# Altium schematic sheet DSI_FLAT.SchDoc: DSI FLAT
size A4; Author: Silvio Navaretti; CompanyName: Arduino SRL; DrawnBy: Silvio Navaretti; Engineer: Silvio Navaretti; Organization: Arduino SRL; DocumentNumber: ASX00083; SheetNumber: 7; SheetTotal: 11; RevAuthor: Silvio Navaretti
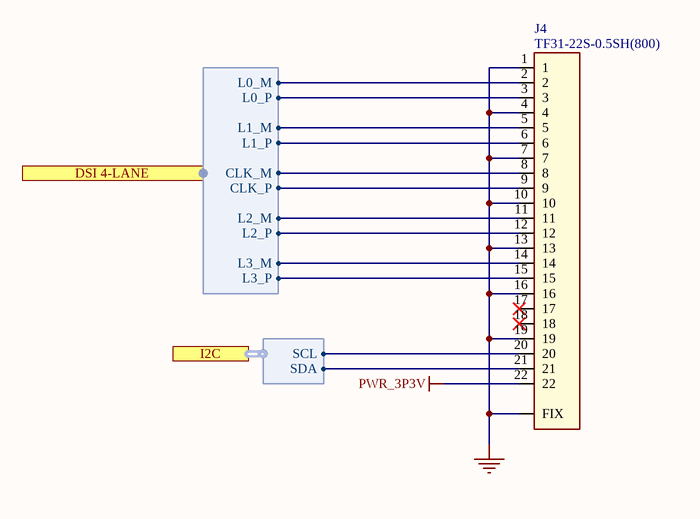
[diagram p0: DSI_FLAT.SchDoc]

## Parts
J4  TF31-22S-0.5SH(800)  [TF31-22S-0.5SH(800)]

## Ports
DSI 4-LANE (harness IMOLA_DSI), I2C (harness I2C)

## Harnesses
I2C: SDA, SCL
IMOLA_DSI: L1_P, L1_M, L3_P, L3_M, CLK_P, CLK_M, L0_P, L0_M, L2_P, L2_M

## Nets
GND: J4.1 J4.4 J4.7 J4.10 J4.13 J4.16 J4.19 J4.FIX
PWR_3P3V: J4.22
NetJ4_2: J4.2 ; port DSI 4-LANE.L0_M
NetJ4_3: J4.3 ; port DSI 4-LANE.L0_P
NetJ4_5: J4.5 ; port DSI 4-LANE.L1_M
NetJ4_6: J4.6 ; port DSI 4-LANE.L1_P
NetJ4_8: J4.8 ; port DSI 4-LANE.CLK_M
NetJ4_9: J4.9 ; port DSI 4-LANE.CLK_P
NetJ4_11: J4.11 ; port DSI 4-LANE.L2_M
NetJ4_12: J4.12 ; port DSI 4-LANE.L2_P
NetJ4_14: J4.14 ; port DSI 4-LANE.L3_M
NetJ4_15: J4.15 ; port DSI 4-LANE.L3_P
NetJ4_20: J4.20 ; port I2C.SCL
NetJ4_21: J4.21 ; port I2C.SDA

Not connected (* = marked no-connect by the designer): J4 17* 18*

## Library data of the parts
J4 = J0553-A.2: CONN FFC/FPC Connector, 22 Contact(s), 1 Row(s), BOTTOM CONTACT, Female, Right Angle, 0.5mm Pitch; Manufacturer: Hirose; Code Arduino: J0553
